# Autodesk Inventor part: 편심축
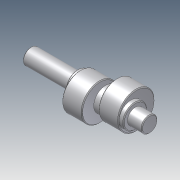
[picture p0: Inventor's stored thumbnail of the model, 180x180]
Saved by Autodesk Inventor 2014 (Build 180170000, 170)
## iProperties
Company: 한국ATC센터
Created: 2014-01
Part Number: 편심축
Document SubType Name: Modeling
Designer: KYOUNG IL JANG
Density: 7.86 g/cm^3
Material: 강철, 연강
Mass: 964.605 g
Surface Area: 190.471 cm^2
Volume: 122.723 cm^3
Vendor: CBT Solutions
Appearance: 강철
Author: KYOUNG IL JANG
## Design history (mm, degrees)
sketch "스케치1"
  geometry: L1 (70, -32)-(70, 32) reference; L2 (87, -18.2)-(87, 18.2) reference; L3 (-62, 0)-(88, 0); L4 (88, 0)-(88, 10); L5 (88, 10)-(70, 10); L6 (70, 10)-(70, 15); L7 (70, 15)-(-3, 15); L8 (-3, 15)-(-3, 10); L9 (-3, 10)-(-62, 10); L10 (-62, 10)-(-62, 0); L11 (66, 70)-(38, 70) reference; L12 (34, 70)-(6, 70) reference; L13 (52, 70)-(52, 15); L14 (20, 70)-(20, 15); 1 further point
  constraints: 20 end point, 6 perpendicular, 5 point on line, 3 parallel, 2 midpoint, 1 collinear
  dimensions: "d0" = 1 distance from line of L3.end L2; "d1" = 20 diameter of L5 L3; "d2" = 30 diameter of L7 L3; "d3" = 73 distance of L6.end L7.end; "d18" = 150 distance of L3.start L3.end
  node "참조1"
  node "참조2"
  node "참조3"
  node "참조4"
revolve "회전1" stored, may be unused: angle "d4" = 90 deg
node "작업 평면1"
sketch "스케치2"
  geometry: C1 r 15 at (70, 0) reference; C2 r 23 at (63, 0); 1 further point
  constraints: 1 centre point, 1 horizontal alignment
  dimensions: "d6" = 7 distance of C2.centre C1.centre; "d7" = 46 diameter of C2
extrude "돌출1" join sketch "스케치2" stored distance "d8" = 25; taper "d9" = 0 deg
node "작업 평면2"
sketch "스케치3"
  geometry: C1 r 15 at (70, 0) reference; C2 r 23 at (77, 0); 1 further point
  constraints: 1 centre point, 1 horizontal alignment
  dimensions: "d11" = 46 diameter of C2 (= d7); "d12" = 7 distance of C2.centre point (70, 0) (= d6)
extrude "돌출2" join sketch "스케치3" stored distance "d13" = 25; taper "d14" = 0 deg
chamfer "모따기1" distance "d15" = 1; stored, may be unused: second distance "d16" = 2, angle "d17" = 45 deg
node "작업 평면3"
sketch "스케치4"
  geometry: L1 (29.5, 9)-(29.5, -9) reference; L2 (29.5, 3)-(12.5, 3); L3 (12.5, -3)-(29.5, -3); A1 r 3 centre (12.5, 0) between (12.5, 3) and (12.5, -3); 2 further points
  constraints: 4 end point, 2 perpendicular, 2 point on circle, 2 point on line, 2 tangent, 1 centre point, 1 horizontal alignment, 1 midpoint
  dimensions: "d19" = 20 dimension on A1 L1; "d20" = 6 distance between parallel lines of L3 L2
extrude "돌출3" cut sketch "스케치4" distance "d21" = 3.5; taper "d22" = 0 deg
chamfer "모따기2" distance "d23" = 1; stored, may be unused: second distance "d24" = 2, angle "d25" = 45 deg
sketch "스케치5"
  geometry: L1 (8.5, 16)-(8.5, -30) reference; L2 (31.5, 16)-(8.5, 16) reference; L3 (8.5, -7)-(100.304, -7); L4 (63.5, 30)-(40.5, 30) reference; L5 (40.5, 30)-(40.5, -16) reference; L6 (40.5, 7)-(102.22, 7); A1 r 30 centre (20, 45.394) between (14, 16) and (26, 16); A2 r 30 centre (52, 59.394) between (46, 30) and (58, 30); 3 further points
  constraints: 4 end point, 4 midpoint, 4 point on circle, 4 point on line, 2 centre point, 2 parallel, 2 vertical alignment, 1 perpendicular
  dimensions: "d27" = 30 radius of A1; "d28" = 6 distance of A1.start point (20, 16); "d30" = 6 distance of A2.start point (52, 30) (= d28); "d31" = 30 radius of A2 (= d27)
node "솔리드1"
other parameters: "d5" = 0, "d10" = 0
